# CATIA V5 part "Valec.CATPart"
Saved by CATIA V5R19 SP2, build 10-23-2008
Part number: Valec
Bounding box of the stored display mesh (mm): x -70 to 70, y -25 to 25, z -70 to 100
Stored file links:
  D:\Catia\Flexible-rigid\Valec.CATPart
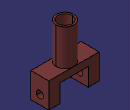
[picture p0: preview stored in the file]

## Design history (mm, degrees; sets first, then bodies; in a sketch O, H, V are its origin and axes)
AxisSystem1: origin (0, 0, 0), X (1, 0, 0), Y (0, 1, 0), Z (0, 0, 1)
Set1
  Sketch1 on XY plane of AxisSystem1, origin (0, 0, 0), H (1, 0, 0), V (0, 1, 0)
    circle A1 centre (0, 0) radius 25
    radius A1 = 25
Body1 (main body)
  Pad1: profile Sketch1, direction (0, 0, 1), length 100, thin wall 5
  Sketch2 on ZX plane of AxisSystem1, origin (0, 0, 0), H (0, 0, 1), V (1, 0, 0)
    line L1 (0, 0) -> (0, -70)
    line L2 (0, -70) -> (-70, -70)
    line L3 (-70, -70) -> (-70, -40)
    line L4 (-70, -40) -> (-20, -40)
    line L5 (-20, -40) -> (-20, 0)
    point P5 (-20, 0)
    line L6 (-20, 0) -> (0, 0)
    vertical: L1 V, L3 V, L5 V
    horizontal: L2 H, L4 H, L6 H
    coincidence: P5 H
  Pad2: profile Sketch2, direction (0, 1, 0), length 25, opposite side length 25
  Sketch3 on face of Pad2 from Sketch2.L2, origin (-70, -0.2184, -44.9577), H (0, 1, 0), V (0, 0, -1)
    point P1 (0, 0)
  Hole1: placed by Sketch3, at (-70, -0.2184, -44.9577) direction (1, 0, 0), diameter 20, through (limit type 6)
  Mirror1: of the body so far, about face of Pad2 from Sketch2.L6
